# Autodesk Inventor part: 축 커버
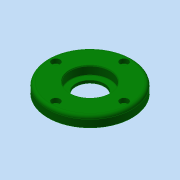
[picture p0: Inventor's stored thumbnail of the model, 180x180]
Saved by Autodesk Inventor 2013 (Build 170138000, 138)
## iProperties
Created: 2015-10
Part Number: 축 커버
Document SubType Name: Modeling
Designer: mdu
Density: 2.71 g/cm^3
Material: 알루미늄 6061
Mass: 115.032 g
Surface Area: 136.578 cm^2
Volume: 42.4472 cm^3
Author: mdu
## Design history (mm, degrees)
sketch "스케치1"
  geometry: C1 r 40 at (0, 0) reference; C2 r 26 at (0, 0) reference; 1 further point
  node "참조1"
  node "참조2"
extrude "돌출1" new body sketch "스케치1" distance "d0" = 10; taper "d1" = 0 deg
extrude "돌출2" join sketch "스케치1" distance "d2" = 4; taper "d3" = 0 deg
hole "구멍1" diameter "d6" = 27; stored, may be unused: countersink angle "d10" = 90 deg, drill point angle "d12" = 118 deg; dims "d7" = 6, "d8" = 38, "d9" = 8.3, "d11" = 8, "d33" = 10, "d34" = 10
sketch "스케치2"
  geometry: C1 r 20 at (0, 0); 1 further point
  constraints: 1 centre point, 1 coincident
  dimensions: "d13" = 40 diameter of C1
extrude "돌출3" cut sketch "스케치2" distance "d14" = 3; taper "d15" = 0 deg
sketch "스케치3"
  geometry: C1 r 1.621 at (0, 32.5) reference; 1 further point
hole "구멍2" sketch "스케치3" at (0, 32.5) diameter "d16" = 4.5; stored, may be unused: countersink angle "d20" = 90 deg, drill point angle "d22" = 118 deg; dims "d17" = 6, "d18" = 8, "d19" = 4.4, "d21" = 8
fillet "모깎기1" dims "d26" = 3, "d27" = 0.3
chamfer "모따기1" distance "d28" = 1; stored, may be unused: second distance "d29" = 2, angle "d30" = 45 deg
chamfer "모따기2" distance "d31" = 0.8; stored, may be unused: second distance "d32" = 2, angle "d35" = 30 deg
node "솔리드1"
pattern_circular "원형 패턴1" dims angle "d24" = 360 deg
node "참조3"
